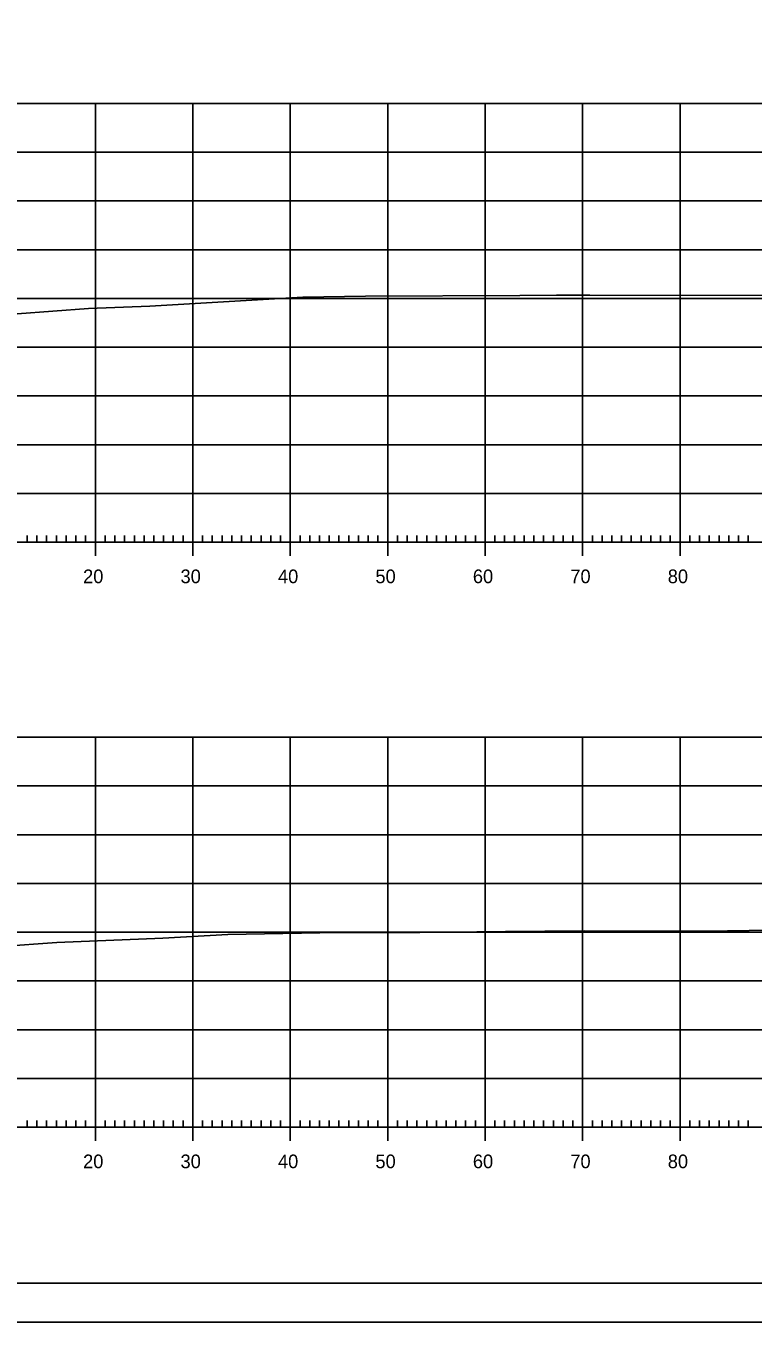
# Model space of a CAD drawing. Extents: x 1360146 to 1361431, y 631444 to 632352.
# Drawn here: x 1361254.5 to 1361329.1, y 631924.1 to 632057 of the extents above; entities that cross this region are included whole.
import ezdxf

# ---------------------------------------------------------------- set-up
doc = ezdxf.new("R2010")
doc.units = 0
for name, color, linetype in [('R_Axis', 7, 'Continuous'), ('R_Axis Annot', 7, 'Continuous'), ('R_Border', 7, 'Continuous'), ('R_Exist Surface', 7, 'Continuous'), ('R_Grid', 7, 'Continuous'), ('R_No Plot', 7, 'Continuous')]:
    doc.layers.add(name, color=color, linetype=linetype)

msp = doc.modelspace()

# ---------------------------------------------------------------- linework, layer by layer
at = {"layer": 'R_Axis'}
for p, q in [((1361101.6, 632004.09), (1361381.6, 632004.09)), ((1361254.6, 632004.09), (1361254.6, 632004.79)), ((1361255.6, 632004.09), (1361255.6, 632004.79)), ((1361256.6, 632004.09), (1361256.6, 632004.79)), ((1361257.6, 632004.09), (1361257.6, 632004.79)), ((1361258.6, 632004.09), (1361258.6, 632004.79)), ((1361259.6, 632004.09), (1361259.6, 632004.79)), ((1361260.6, 632004.09), (1361260.6, 632004.79)), ((1361261.6, 632002.69), (1361261.6, 632004.09)), ((1361262.6, 632004.09), (1361262.6, 632004.79)), ((1361263.6, 632004.09), (1361263.6, 632004.79)), ((1361264.6, 632004.09), (1361264.6, 632004.79)), ((1361265.6, 632004.09), (1361265.6, 632004.79)), ((1361266.6, 632004.09), (1361266.6, 632004.79)), ((1361267.6, 632004.09), (1361267.6, 632004.79)), ((1361268.6, 632004.09), (1361268.6, 632004.79)), ((1361269.6, 632004.09), (1361269.6, 632004.79)), ((1361270.6, 632004.09), (1361270.6, 632004.79)), ((1361271.6, 632002.69), (1361271.6, 632004.09)), ((1361272.6, 632004.09), (1361272.6, 632004.79)), ((1361273.6, 632004.09), (1361273.6, 632004.79)), ((1361274.6, 632004.09), (1361274.6, 632004.79)), ((1361275.6, 632004.09), (1361275.6, 632004.79)), ((1361276.6, 632004.09), (1361276.6, 632004.79)), ((1361277.6, 632004.09), (1361277.6, 632004.79)), ((1361278.6, 632004.09), (1361278.6, 632004.79)), ((1361279.6, 632004.09), (1361279.6, 632004.79)), ((1361280.6, 632004.09), (1361280.6, 632004.79)), ((1361281.6, 632002.69), (1361281.6, 632004.09)), ((1361282.6, 632004.09), (1361282.6, 632004.79)), ((1361283.6, 632004.09), (1361283.6, 632004.79)), ((1361284.6, 632004.09), (1361284.6, 632004.79)), ((1361285.6, 632004.09), (1361285.6, 632004.79)), ((1361286.6, 632004.09), (1361286.6, 632004.79)), ((1361287.6, 632004.09), (1361287.6, 632004.79)), ((1361288.6, 632004.09), (1361288.6, 632004.79)), ((1361289.6, 632004.09), (1361289.6, 632004.79)), ((1361290.6, 632004.09), (1361290.6, 632004.79)), ((1361291.6, 632002.69), (1361291.6, 632004.09)), ((1361292.6, 632004.09), (1361292.6, 632004.79)), ((1361293.6, 632004.09), (1361293.6, 632004.79)), ((1361294.6, 632004.09), (1361294.6, 632004.79)), ((1361295.6, 632004.09), (1361295.6, 632004.79)), ((1361296.6, 632004.09), (1361296.6, 632004.79)), ((1361297.6, 632004.09), (1361297.6, 632004.79)), ((1361298.6, 632004.09), (1361298.6, 632004.79)), ((1361299.6, 632004.09), (1361299.6, 632004.79)), ((1361300.6, 632004.09), (1361300.6, 632004.79)), ((1361301.6, 632002.69), (1361301.6, 632004.09)), ((1361302.6, 632004.09), (1361302.6, 632004.79)), ((1361303.6, 632004.09), (1361303.6, 632004.79)), ((1361304.6, 632004.09), (1361304.6, 632004.79)), ((1361305.6, 632004.09), (1361305.6, 632004.79)), ((1361306.6, 632004.09), (1361306.6, 632004.79)), ((1361307.6, 632004.09), (1361307.6, 632004.79)), ((1361308.6, 632004.09), (1361308.6, 632004.79)), ((1361309.6, 632004.09), (1361309.6, 632004.79)), ((1361310.6, 632004.09), (1361310.6, 632004.79)), ((1361311.6, 632002.69), (1361311.6, 632004.09)), ((1361312.6, 632004.09), (1361312.6, 632004.79)), ((1361313.6, 632004.09), (1361313.6, 632004.79)), ((1361314.6, 632004.09), (1361314.6, 632004.79)), ((1361315.6, 632004.09), (1361315.6, 632004.79)), ((1361316.6, 632004.09), (1361316.6, 632004.79)), ((1361317.6, 632004.09), (1361317.6, 632004.79)), ((1361318.6, 632004.09), (1361318.6, 632004.79)), ((1361319.6, 632004.09), (1361319.6, 632004.79)), ((1361320.6, 632004.09), (1361320.6, 632004.79)), ((1361321.6, 632002.69), (1361321.6, 632004.09)), ((1361322.6, 632004.09), (1361322.6, 632004.79)), ((1361323.6, 632004.09), (1361323.6, 632004.79)), ((1361324.6, 632004.09), (1361324.6, 632004.79)), ((1361325.6, 632004.09), (1361325.6, 632004.79)), ((1361326.6, 632004.09), (1361326.6, 632004.79)), ((1361327.6, 632004.09), (1361327.6, 632004.79)), ((1361328.6, 632004.09), (1361328.6, 632004.79)), ((1361254.6, 631944.09), (1361254.6, 631944.79)), ((1361255.6, 631944.09), (1361255.6, 631944.79)), ((1361256.6, 631944.09), (1361256.6, 631944.79)), ((1361257.6, 631944.09), (1361257.6, 631944.79)), ((1361258.6, 631944.09), (1361258.6, 631944.79)), ((1361259.6, 631944.09), (1361259.6, 631944.79)), ((1361260.6, 631944.09), (1361260.6, 631944.79)), ((1361262.6, 631944.09), (1361262.6, 631944.79)), ((1361263.6, 631944.09), (1361263.6, 631944.79)), ((1361264.6, 631944.09), (1361264.6, 631944.79)), ((1361265.6, 631944.09), (1361265.6, 631944.79)), ((1361266.6, 631944.09), (1361266.6, 631944.79)), ((1361267.6, 631944.09), (1361267.6, 631944.79)), ((1361268.6, 631944.09), (1361268.6, 631944.79)), ((1361269.6, 631944.09), (1361269.6, 631944.79)), ((1361270.6, 631944.09), (1361270.6, 631944.79)), ((1361272.6, 631944.09), (1361272.6, 631944.79)), ((1361273.6, 631944.09), (1361273.6, 631944.79)), ((1361274.6, 631944.09), (1361274.6, 631944.79)), ((1361275.6, 631944.09), (1361275.6, 631944.79)), ((1361276.6, 631944.09), (1361276.6, 631944.79)), ((1361277.6, 631944.09), (1361277.6, 631944.79)), ((1361278.6, 631944.09), (1361278.6, 631944.79)), ((1361279.6, 631944.09), (1361279.6, 631944.79)), ((1361280.6, 631944.09), (1361280.6, 631944.79)), ((1361282.6, 631944.09), (1361282.6, 631944.79)), ((1361283.6, 631944.09), (1361283.6, 631944.79)), ((1361284.6, 631944.09), (1361284.6, 631944.79)), ((1361285.6, 631944.09), (1361285.6, 631944.79)), ((1361286.6, 631944.09), (1361286.6, 631944.79)), ((1361287.6, 631944.09), (1361287.6, 631944.79)), ((1361288.6, 631944.09), (1361288.6, 631944.79)), ((1361289.6, 631944.09), (1361289.6, 631944.79)), ((1361290.6, 631944.09), (1361290.6, 631944.79)), ((1361292.6, 631944.09), (1361292.6, 631944.79)), ((1361293.6, 631944.09), (1361293.6, 631944.79)), ((1361294.6, 631944.09), (1361294.6, 631944.79)), ((1361295.6, 631944.09), (1361295.6, 631944.79)), ((1361296.6, 631944.09), (1361296.6, 631944.79)), ((1361297.6, 631944.09), (1361297.6, 631944.79)), ((1361298.6, 631944.09), (1361298.6, 631944.79)), ((1361299.6, 631944.09), (1361299.6, 631944.79)), ((1361300.6, 631944.09), (1361300.6, 631944.79)), ((1361302.6, 631944.09), (1361302.6, 631944.79)), ((1361303.6, 631944.09), (1361303.6, 631944.79)), ((1361304.6, 631944.09), (1361304.6, 631944.79)), ((1361305.6, 631944.09), (1361305.6, 631944.79)), ((1361306.6, 631944.09), (1361306.6, 631944.79)), ((1361307.6, 631944.09), (1361307.6, 631944.79)), ((1361308.6, 631944.09), (1361308.6, 631944.79)), ((1361309.6, 631944.09), (1361309.6, 631944.79)), ((1361310.6, 631944.09), (1361310.6, 631944.79)), ((1361312.6, 631944.09), (1361312.6, 631944.79)), ((1361313.6, 631944.09), (1361313.6, 631944.79)), ((1361314.6, 631944.09), (1361314.6, 631944.79)), ((1361315.6, 631944.09), (1361315.6, 631944.79)), ((1361316.6, 631944.09), (1361316.6, 631944.79)), ((1361317.6, 631944.09), (1361317.6, 631944.79)), ((1361318.6, 631944.09), (1361318.6, 631944.79)), ((1361319.6, 631944.09), (1361319.6, 631944.79)), ((1361320.6, 631944.09), (1361320.6, 631944.79)), ((1361322.6, 631944.09), (1361322.6, 631944.79)), ((1361323.6, 631944.09), (1361323.6, 631944.79)), ((1361324.6, 631944.09), (1361324.6, 631944.79)), ((1361325.6, 631944.09), (1361325.6, 631944.79)), ((1361326.6, 631944.09), (1361326.6, 631944.79)), ((1361327.6, 631944.09), (1361327.6, 631944.79)), ((1361328.6, 631944.09), (1361328.6, 631944.79)), ((1361101.6, 631944.09), (1361381.6, 631944.09)), ((1361261.6, 631942.69), (1361261.6, 631944.09)), ((1361271.6, 631942.69), (1361271.6, 631944.09)), ((1361281.6, 631942.69), (1361281.6, 631944.09)), ((1361291.6, 631942.69), (1361291.6, 631944.09)), ((1361301.6, 631942.69), (1361301.6, 631944.09)), ((1361311.6, 631942.69), (1361311.6, 631944.09)), ((1361321.6, 631942.69), (1361321.6, 631944.09))]:
    msp.add_line(p, q, dxfattribs=at)
at = {"layer": 'R_Border'}
msp.add_line((1361398.78, 631928.09), (1361082.6, 631928.09), dxfattribs=at)
at = {"layer": 'R_Exist Surface'}
for points in [[(1361253.58, 632027.5), (1361260.88, 632028.05), (1361267.2, 632028.29), (1361282.88, 632029.21), (1361289.33, 632029.32), (1361305.17, 632029.39), (1361308.93, 632029.42), (1361312.36, 632029.44), (1361331.87, 632029.41), (1361333.05, 632029.48), (1361340.21, 632029.87), (1361346.43, 632030.23), (1361348.66, 632030.32), (1361359.35, 632030.44), (1361365.45, 632030.66), (1361369.26, 632031.08), (1361378.42, 632031.41), (1361381.6, 632031.63)], [(1361251.95, 631962.62), (1361257.64, 631963.05), (1361268.52, 631963.47), (1361275.2, 631963.86), (1361286.53, 631964.05), (1361294.89, 631964.08), (1361303.7, 631964.15), (1361311.75, 631964.22), (1361324.29, 631964.19), (1361330.9, 631964.29), (1361343.34, 631964.54), (1361347.44, 631964.73), (1361363.33, 631964.95), (1361363.54, 631964.96), (1361364.12, 631964.97), (1361375.92, 631965.49), (1361381.44, 631965.5), (1361381.6, 631965.51)]]:
    msp.add_lwpolyline(points, dxfattribs=at)
at = {"layer": 'R_Grid'}
for p, q in [((1361101.6, 632049.09), (1361381.6, 632049.09)), ((1361261.6, 632004.09), (1361261.6, 632049.09)), ((1361271.6, 632004.09), (1361271.6, 632049.09)), ((1361281.6, 632004.09), (1361281.6, 632049.09)), ((1361291.6, 632004.09), (1361291.6, 632049.09)), ((1361301.6, 632004.09), (1361301.6, 632049.09)), ((1361311.6, 632004.09), (1361311.6, 632049.09)), ((1361321.6, 632004.09), (1361321.6, 632049.09)), ((1361101.6, 632044.09), (1361381.6, 632044.09)), ((1361101.6, 632039.09), (1361381.6, 632039.09)), ((1361101.6, 632034.09), (1361381.6, 632034.09)), ((1361101.6, 632029.09), (1361381.6, 632029.09)), ((1361101.6, 632024.09), (1361381.6, 632024.09)), ((1361101.6, 632019.09), (1361381.6, 632019.09)), ((1361101.6, 632014.09), (1361381.6, 632014.09)), ((1361101.6, 632009.09), (1361381.6, 632009.09)), ((1361101.6, 632004.09), (1361381.6, 632004.09)), ((1361101.6, 631984.09), (1361381.6, 631984.09)), ((1361261.6, 631944.09), (1361261.6, 631984.09)), ((1361271.6, 631944.09), (1361271.6, 631984.09)), ((1361281.6, 631944.09), (1361281.6, 631984.09)), ((1361291.6, 631944.09), (1361291.6, 631984.09)), ((1361301.6, 631944.09), (1361301.6, 631984.09)), ((1361311.6, 631944.09), (1361311.6, 631984.09)), ((1361321.6, 631944.09), (1361321.6, 631984.09)), ((1361101.6, 631979.09), (1361381.6, 631979.09)), ((1361101.6, 631974.09), (1361381.6, 631974.09)), ((1361101.6, 631969.09), (1361381.6, 631969.09)), ((1361101.6, 631964.09), (1361381.6, 631964.09)), ((1361101.6, 631959.09), (1361381.6, 631959.09)), ((1361101.6, 631954.09), (1361381.6, 631954.09)), ((1361101.6, 631949.09), (1361381.6, 631949.09)), ((1361101.6, 631944.09), (1361381.6, 631944.09))]:
    msp.add_line(p, q, dxfattribs=at)
at = {"layer": 'R_No Plot'}
msp.add_line((1361070.2, 631924.11), (1361403.53, 631924.11), dxfattribs=at)
for points in [[(1361070.19, 632137.45), (1361403.53, 632137.45), (1361403.53, 631924.11), (1361070.19, 631924.11)], [(1361316.52, 632133.55), (1361316.52, 632123.67), (1361352.25, 632123.67), (1361352.25, 632120.75), (1361375.45, 632120.75), (1361375.45, 632096.42), (1361398.78, 632096.42), (1361398.78, 631928.09), (1361082.6, 631928.09), (1361082.6, 632133.55)]]:
    msp.add_lwpolyline(points, close=True, dxfattribs=at)

# ---------------------------------------------------------------- texts
at = {"layer": 'R_Axis Annot'}
for s, p in [('20', (1361260.34, 631999.89)), ('30', (1361270.34, 631999.89)), ('40', (1361280.34, 631999.89)), ('50', (1361290.34, 631999.89)), ('60', (1361300.34, 631999.89)), ('70', (1361310.34, 631999.89)), ('80', (1361320.34, 631999.89)), ('20', (1361260.34, 631939.89)), ('30', (1361270.34, 631939.89)), ('40', (1361280.34, 631939.89)), ('50', (1361290.34, 631939.89)), ('60', (1361300.34, 631939.89)), ('70', (1361310.34, 631939.89)), ('80', (1361320.34, 631939.89))]:
    msp.add_text(s, height=1.4, dxfattribs=at).set_placement(p)

doc.saveas('drawing.dxf')
